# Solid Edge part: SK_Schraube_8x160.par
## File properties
Author: hStrempfl
Template: Iso Metric Part.par
Last saved by: hStrempfl
Revision: 7
Application: Solid Edge
Genauigkeit: 0,990
Username: hStrempfl
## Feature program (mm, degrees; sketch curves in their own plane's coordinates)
sketch for "unnamed RevolvedProtrusion 1" plane through (0, 0, 0) normal (1, 0, 0) x-axis (0, 1, 0)
  line (0, -160) -> (4, -153.0718)
  line (4, -153.0718) -> (4, -4.5)
  line (7.5, -1) -> (4, -4.5)
  line (7.5, 0) -> (7.5, -1)
  line (7.5, 0) -> (0, 0)
  dimension (linear) = 7.5
  dimension (linear) = 7.5
revolve "unnamed RevolvedProtrusion 1" add full turn 360 deg about sketch line (0, 0) -> (0, -160)
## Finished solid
Body 1: solid body, 5 faces, 4 edges, 1 vertex.
  Faces by surface: cone 2, cylinder 2, plane 1
  Edges by curve: circle 4
Bounding box of the edges (mm): 15.000 x 15.000 x 153.072, from (-7.5, -7.5, -153.0718) to (7.5, 7.5, 0).
Cylindrical faces by radius (mm): R4 x1, R7.5 x1
Conical faces (half-angle, radius in mm at the cone's reference point): 30 deg R0 x1, 45 deg R4 x1
Planar faces by outward normal: +z 1
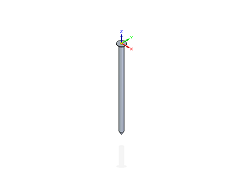
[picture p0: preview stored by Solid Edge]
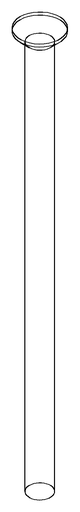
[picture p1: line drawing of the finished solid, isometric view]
